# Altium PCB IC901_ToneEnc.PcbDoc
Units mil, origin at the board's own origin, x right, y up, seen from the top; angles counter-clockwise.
Board outline 1200 x 900 mil, 2 copper layers (Top Layer, Bottom Layer), stack 30.2 mil thick; 35 components, 32 nets, 99 pads, 51 vias.
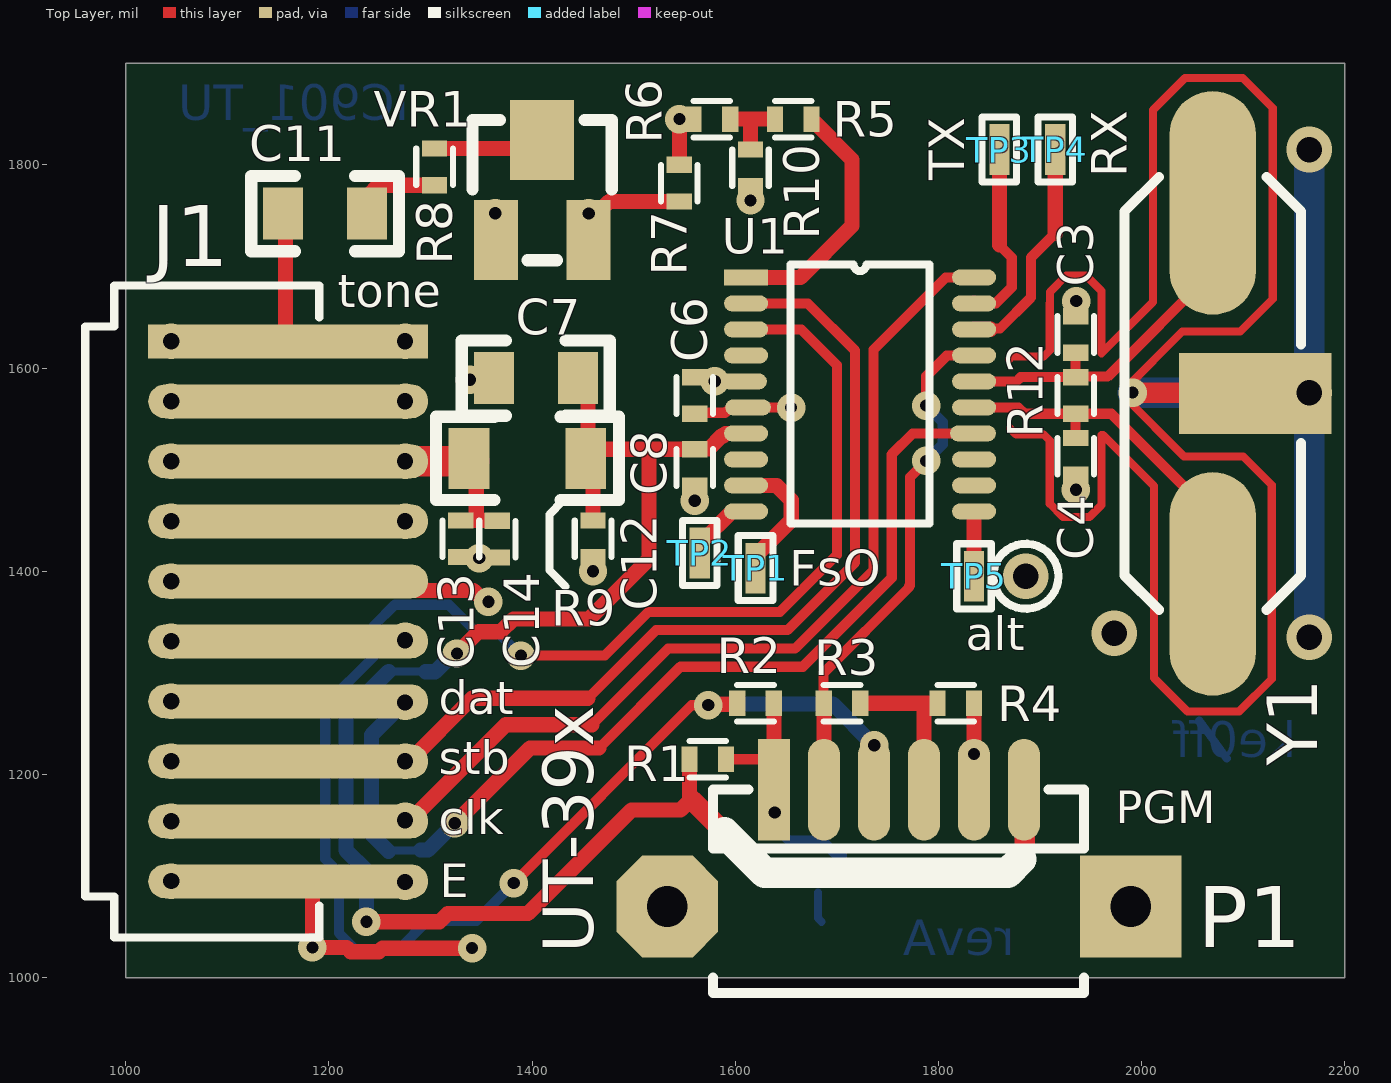
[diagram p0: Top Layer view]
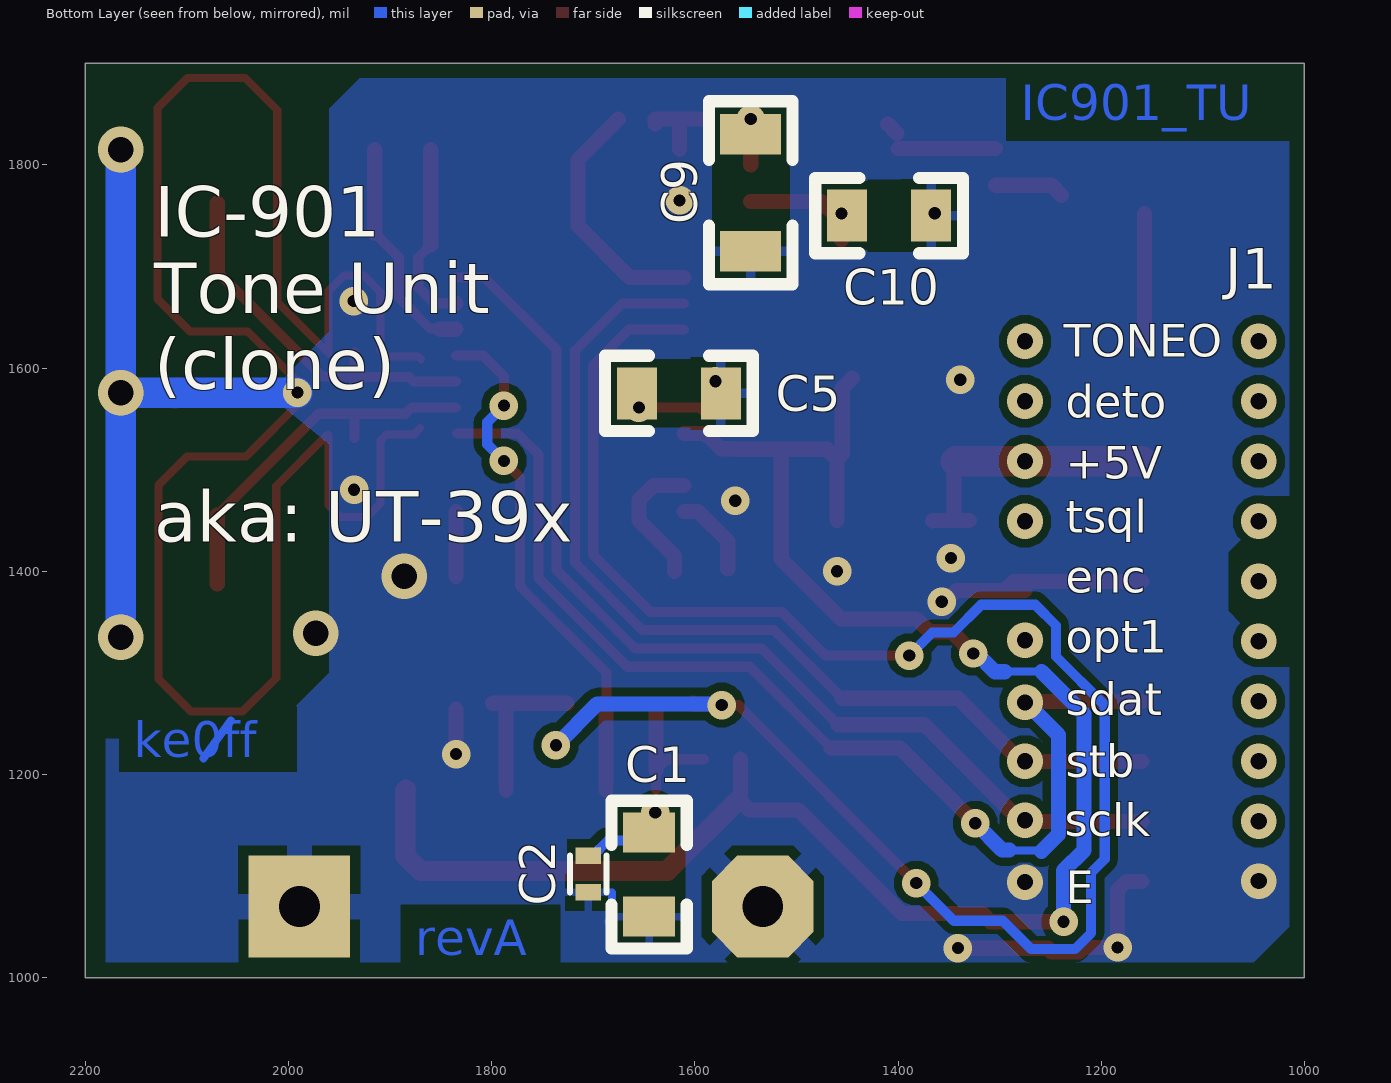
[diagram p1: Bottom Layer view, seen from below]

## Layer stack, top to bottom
Top Solder: solder mask 0.4, Solder Resist, Dk 3.5
Top Layer: signal copper 1.4
Dielectric 1: dielectric 27.4, FR-4, Dk 4.8
Bottom Layer: signal copper 1.4
Bottom Solder: solder mask 0.4, Solder Resist, Dk 3.5

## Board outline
1000,1000 1000,1900 2200,1900 2200,1000

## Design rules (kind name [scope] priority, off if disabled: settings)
Clearance [All] p1: gap=8 ignorepadtopadclearanceinfootprint=FALSE
HoleSize [All] p1: absolutevalues=TRUE maxlimit=275 minlimit=12 maxpercent=80.000 minpercent=20.000
MinimumSolderMaskSliver [All] p1: minsoldermaskwidth=1
NetAntennae [All] p1: netantennaetolerance=400
PolygonConnect PolygonConnect_2 [IsVia] p1: connectstyle=Direct reliefconductorwidth=10 reliefentries=4 polygonreliefangle="90 Angle" airgapwidth=10
PolygonConnect [IsPad] p2: connectstyle=Relief reliefconductorwidth=20 reliefentries=4 polygonreliefangle="45 Angle" airgapwidth=10
PolygonConnect PolygonConnect_1 [All] p3: connectstyle=Relief reliefconductorwidth=10 reliefentries=4 polygonreliefangle="90 Angle" airgapwidth=10
RoomDefinition IC901_ToneEnc [InComponentClass('IC901_ToneEnc')] p1: confinementstyle=ConfineOut formatcopy=TRUE lockcomponents=FALSE outline 0,0 445,0 445,200 0,200
RoutingVias [All] p1: holewidth=12 width=25 viastyle="Through Hole" minholewidth=12 minwidth=24 maxholewidth=100 maxwidth=150
SilkToSilkClearance [All] p1: silktosilkclearance=0
SilkToSolderMaskClearance [IsPad] p1: minsilkscreentomaskgap=0 clearancetoexposedcopper=TRUE
SolderMaskExpansion [All] p1: expansion=4 istentingtop=FALSE
Width [All] p1: maxlimit=100 minlimit=8 preferedwidth=10 minimp=50.000000 maximp=50.000000 favimp=50.000000
25 further rules are at their usual default settings.

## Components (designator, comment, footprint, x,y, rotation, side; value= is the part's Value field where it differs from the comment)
C1 "1.0uF" 0805 1645,1142.68 r270 bottom
C2 "0.1uF" 0402 1705,1120 r270 bottom
C3 "22pF" 0402 1935,1615 r90 top
C4 "22pF" 0402 1935,1531 r270 top
C5 "4.7uF" 0805 1657,1575 r180 bottom
C6 "0.1uF" 0402 1560,1555 r90 top
C7 "4.7uF" 0805 1445,1590 r180 top
C8 "0.1uF" 0402 1560,1520 r270 top
C9 "0.047uF" 1206 1545,1830 r270 bottom
C10 "4700pF" 0805 1450,1750 r180 bottom
C11 "1.0uF" 0805 1237.68,1752 r180 top
C12 "0.1uF" 0402 1460,1450 r270 top
C13 "0.1uF" 0402 1330,1450 r270 top
C14 "1000pF" 0402 1365.88,1449.61 r270 top
J1 "TONE" MOLEX_1.5MM_SMD_10POS 1160,1094.72 r0 top
P1 "PGM" CON_1.25MM_6P 1638.15,1185 r0 top
R1 "1.00K" 0402 1591,1215 r180 top
R2 "1.00K" 0402 1602,1270 r0 top
R3 "1.00K" 0402 1687,1270 r0 top
R4 "100K" 0402 1835,1270 r180 top
R5 "499" 0402 1639,1845 r0 top
R6 "909" 0402 1559,1845 r0 top
R7 "13.7K" 0402 1545,1764 r90 top
R8 "47K" 0402 1304,1780 r90 top
R9 "10" 1206 1338,1511 r0 top
R10 "330" 0402 1615,1815 r270 top
R12 "10.0M" 0402 1935,1591 r270 top
TP1 "FsO" TP-SMD-20x50-SQ 1620,1403 r180 top
TP2 "SPr15" TP-SMD-20x50-SQ 1565,1418 r180 top
TP3 "TX" TP-SMD-20x50-SQ 1860,1815 r180 top
TP4 "RX" TP-SMD-20x50-SQ 1915,1815 r180 top
TP5 "SPr14" TP-SMD-20x50-SQ 1835,1395 r180 top
U1 "C8051F530" TSSOP-20 1610.59,1689.13 r0 top
VR1 "47K" POT_3313 1364.5,1726 r180 top
Y1 "3.5795M" XTAL_AT49_SMD 2070,1575 r90 top

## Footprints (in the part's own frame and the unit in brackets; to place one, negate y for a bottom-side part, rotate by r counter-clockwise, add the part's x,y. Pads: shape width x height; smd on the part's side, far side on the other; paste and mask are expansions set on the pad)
0402 [mil]
  rect 16x25 smd mask+2: 1(0,0) 2(36,0)
  silkscreen extent 0,-18 36,18, body extent -2,-10 38,10, height 10
0805 [mm]
  rect 1x1.3 smd: 1(0,0) 2(2.1,0)
  silkscreen extent -0.8,-0.94 2.9,0.94, body extent -0.03,-0.64 2.13,0.63, height 0.51
1206 [mil]
  rect 40x60 smd: 1(0,0) 2(115,0)
  silkscreen extent -33,-41 148,41, body extent -3,-30 117,30, height 30
CON_1.25MM_6P [mm]
  rect 0.8x2.54 smd: 1(0,0)
  oval 0.8x2.54 smd: 2(1.25,0) 3(2.5,0) 4(3.75,0) 5(5,0) 6(6.25,0)
  oct 2.54x2.54 hole 1.016: 7(-2.667,-2.921)
  rect 2.54x2.54 hole 1.016: 8(8.915,-2.921)
  silkscreen extent -1.52,-5.08 7.75,0, body extent -2.96,-4.41 9.19,0.49, height 4.79
MOLEX_1.5MM_SMD_10POS [mm]
  rect 7x0.85 smd mask-10: 1(0,13.5)
  oval 7x0.85 smd mask-10: 2(0,12) 3(0,10.5) 4(0,9) 5(0,7.5) 6(0,6) 7(0,4.5) 8(0,3) 9(0,1.5) 10(0,0)
  silkscreen extent -5.07,-1.4 0.77,14.9, body extent -5.02,-1.4 2.73,14.9, height 4.52
POT_3313 [mil]
  rect 43x78.74 smd: 1(0,0) 3(-91,0)
  rect 63x78.74 smd: 2(-45.5,-98.27)
  silkscreen extent -114,-118 23,20, body extent -108,-118 22,20, height 87
TP-SMD-20x50-SQ [mil]
  rect 20x50 smd mask+2: 1(0,0)
  silkscreen extent -17,-32 17,32
TSSOP-20 [mm]
  rect 1.1x0.4 smd mask+0.051: 1(0,0)
  oval 1.1x0.4 smd mask+0.051: 2(0,-0.65) 3(0,-1.3) 4(0,-1.95) 7(0,-3.9) 8(0,-4.55) 9(0,-5.2) 10(0,-5.85) 11(5.7,-5.85) 12(5.7,-5.2) 13(5.7,-4.55) 15(5.7,-3.25) 16(5.7,-2.6) 17(5.7,-1.95) 18(5.7,-1.3) 19(5.7,-0.65) 20(5.7,0)
  oval 1.143x0.4 smd mask+0.051: 5(-0.051,-2.6) 6(0.051,-3.25) 14(5.675,-3.9)
  silkscreen extent 1.11,-6.15 4.59,0.32, body extent -0.35,-6.1 6.05,0.27, height 1.2
XTAL_AT49_SMD [mil]
  oval 220x85 smd mask+2: 1(-187.5,0) 2(187.5,0)
  rect 80x150 smd mask+2: 3(0,-42)
  silkscreen extent -213,-87 213,87, body extent -276,-87 276,87, height 134

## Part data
C1 C11: library part "CAP 0805", "CAP, CER, 0805, 1.0uF, 25V", MFR=Samsung, MPN=CL21B105KBFNNNF, Voltage=25V
C2 C6 C8 C12 C13: library part "CAP CER", "CAP, CER, 0402, 0.1uF, 50V", MFR=AVX, MPN=04025C104KAT2A
C3 C4: library part "CAP 0805", "CAP, MLCC, NPO, 1%, 0402, 50V, 22pF", MFR=Murata, MPN=GCM1555C1H220FA16D, Voltage=50
C5 C7: library part "CAP 0805", "CAP, CER, 0805, 4.7uF, 10V", MFR=TDK, MPN=C2012X7R1A475K125AC, Voltage=10V
C9: library part "CAP 0805", "CAP, CER, NPO, 0805, 50V, 47nF", MFR=Yageo, MPN=CC1206JKNPO9BN473, Voltage=50V
C10: library part "CAP 0805", "CAP, CER, 0805, NPO, 50V, 4700pF", MFR=Walsin, MPN=0805N472J500CT, Voltage=50V
C14: library part "CAP CER", "CAP, CER, 0402, 50V, 1000pF", MFR=Yageo, MPN=CC0402JRNPO9BN102
J1: library part CON10, "CON, 10POS, 1.5mm, RTANG, SMT", MFR=Molex, MPN=87438-1043
P1: library part HEADER-6-PIN-RT-ANG, "CON, 6POS, 1.25MM, SMD", MFR=Molex, MPN=53398-0671
R1 R2 R3: library part R0805, "RES, CHP, 0402, 1%, 1K", MFR=Yageo, MPN=RC0402FR-071KL
R4: library part R0805, "RES, CHP, 0402, 1%, 100K", MFR=Yageo, MPN=RC0402FR-07100KL
R5: library part R0805, "RES, CHP, 0402, 1%, 499", MFR=Yageo, MPN=RC0402FR-07499RL
R6: library part R0805, "RES, CHP, 0402, 1%, 909", MFR=Yageo, MPN=RC0402FR-07909RL
R7: library part R0805, "RES, CHP, 0402, 1%, 13.7K", MFR=Yageo, MPN=RC0402FR-0713K7L
R8: library part R0805, "RES, CHP, 0402, 1%, 47K", MFR=Yageo, MPN=RC0402FR-0747KL
R9: library part R0805, "RES, CHP, 0402, 1%, 10.0", MFR=Yageo, MPN=RC1206FR-7W10RL
R10: library part R0805, "RES, CHP, 0402, 1%, 330", MFR=Yageo, MPN=RC0402FR-07330RL
R12: library part R0805, "RES, CHP, 0402, 1%, 10.0M", MPN=RC0402FR-0710ML
TP1 TP2 TP3 TP4 TP5: library part TP
U1: library part C8051F531, "IC, MCU, 8051, F531", MFR=SiLabs, MPN=C8051F531-C-IT
VR1: library part "RESISTOR VAR", MFR=Bourns, MPN=3313X-1-503E
Y1: library part CRYSTAL-2PIN, "CRYSTAL 2 PIN", MFR=Abracon, MPN=ABLSG-3.579545MHZ-D2Y-T

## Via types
v1: diameter 28, hole 12, Top Layer to Bottom Layer, tented both sides, 27 vias
v2: diameter 35, hole 16, Top Layer to Bottom Layer, 19 vias
v3: diameter 45, hole 25, Top Layer to Bottom Layer, 5 vias

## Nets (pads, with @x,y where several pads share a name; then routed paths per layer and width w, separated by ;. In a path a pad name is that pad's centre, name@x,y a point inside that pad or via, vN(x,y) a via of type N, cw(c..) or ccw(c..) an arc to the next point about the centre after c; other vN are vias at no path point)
+5V_IN: C13.1 C14.1 J1.3 R9.1 | length 283.2
  Top Layer w15: C13.1 1330.2,1449.8 1347.94,1449.8 ; R9.1@1336.11,1509.11 R9.1 ; R9.1@1345,1510 1345,1452.74 1347.94,1449.8 ; C14.1 1365.68,1449.8 1347.94,1449.8
  Top Layer w30: J1.3 v2(1275,1508.11) R9.1@1343.11,1508.11
  other v2: 1045,1508.11
/RESET: C1.1 C2.1 P1.1 R1.1 R2.2 | length 199.3
  Top Layer w10: R1.1 1627.4,1215 1638.15,1204.25 P1.1
  Top Layer w15: P1.1@1638.15,1204.25 R2.2@1638.15,1263.35
  Bottom Layer w10: C1.1 1652.68,1135 1685.5,1135 1700.5,1120 C2.1
  other v1: 1638.92,1162.44
/RST_C2K: P1.3 R2.1 U1.3 | length 1812.7
  Top Layer w10: v1(1382,1093) 1557,1268 v1@1563.4,1268 ; v1(1389,1317) 1471.54,1317 1514.54,1360 1644,1360 1700,1416 1700,1603 1665.05,1637.95 U1.3
  Top Layer w15: v1(1573.44,1268.28) 1574.31,1269.14 1601.5,1269.14 1602,1269.64 R2.1
  Bottom Layer w10: v1(1382,1093) 1345,1056 1296.97,1056 1268.97,1028 1225.82,1028 1210,1043.82 1210,1103.27 1196.5,1116.77 1196.5,1268.05 1244.5,1316.05 1244.5,1346.5 1265,1367 1318,1367 1345.31,1339.69 1366.31,1339.69 v1(1389,1317)
  Bottom Layer w15: v1@1574.44,1269.27 1696.07,1269.27 v1(1736.73,1228.61)
DETO: J1.2
  other v2: 1045,1567.17 1275,1567.17
fsamp_out: TP1.1 U1.9 | length 134.9
  Top Layer w15: U1.9 1610.73,1484.27 1640.73,1484.27 1655,1470 1655,1450 1620,1415 TP1.1@1620,1400
GND: C1.2 C2.2 C3.2 C4.2 C5.2 C6.2 C7.2 C8.2 C9.2 C10.2 C12.2 C13.2 C14.2 J1.5 J1.10 P1.5 P1.7 P1.8 R4.1 R10.2 U1.5 VR1.1 Y1.3 | length 3342.3
  Top Layer w8: 1869.65,1608.64 1872.51,1611.5 1903.64,1611.5 1909.5,1617.36 1909.5,1649.75 1909.5,1663.77 1909.65,1663.92 1909.65,1674.91 1925.77,1691.03 1945.11,1691.03 1960.5,1675.63 1960.5,1638.38 1960.5,1614.5 2011,1664.99 2011,1854 2042.5,1885.5 2099.5,1885.5 2129,1856 2129,1668 2097,1636 2039.99,1636 v1@1983.51,1579.52 ; 1870.33,1540.68 1876.51,1534.5 1903.64,1534.5 1909.5,1528.64 1909.5,1466.46 1922.73,1453.23 1948.7,1453.23 1960.5,1465.03 1960.5,1534 ; 1962.01,1534 2012,1484.01 2012,1295 2045,1262 2096,1262 2128,1294 2128,1485 2100,1513 2041.75,1513 v1@1983.51,1571.23
  Top Layer w10: v1@1935,1661 C3.2@1938,1658 ; v1@1983.51,1571.23 v1@1983.51,1579.52
  Top Layer w15: J1.10 1175.35,1094.72 1183.88,1086.19 v1(1183.88,1029.63) 1217.39,1029.63 1221.53,1025.5 1249.22,1025.5 1252.72,1029 v1(1341,1029) ; J1.5 1286.06,1390 J1.5@1295.06,1381 ; J1.5@1275.06,1381 1342.48,1381 1353.48,1370 v1(1357,1370) ; v1(1835,1220) R4.1@1835,1264.5
  Top Layer w20: v1(1991.1,1575.76) Y1.3@2108.24,1575.76
  Top Layer w30: Y1.3@2108.24,1575.76 Y1.3
  Bottom Layer w8: 1681.42,1083.93 1681.42,1058.58 1685,1055
  Bottom Layer w30: v1(1991.1,1575.76) v3(2165,1575.76) ; v3(2165,1335) v3(2165,1575.76) ; v3(2165,1815) v3(2165,1575.76)
  other v1: 1460,1400 1347.95,1412.96 1560.19,1469.27 1935.34,1480.13 1579.75,1586.88 1338.81,1588.4 1935.6,1665.85 1363.81,1752.38 1615,1765
  other v2: 1275,1094 1045,1095 1045,1390
  other v3: 1973,1339 1886,1395
M5V: C7.1 C8.1 C12.1 P1.6 R1.2 R9.2 U1.7 | length 1829.5
  Top Layer w15: v1(1237,1055) 1309,1055 1317,1063 1396,1063 1498,1165 1546.21,1165 1555,1173.79 1555,1176.95 ; v1(1326,1319) 1347.5,1340.5 1369.22,1340.5 1381.72,1353 1456,1353 1515,1412 1515,1520 ; C7.1 1455,1580 1455,1515 R9.2@1460,1510 ; C12.1 R9.2@1460,1510 ; R1.2 1555,1176.95 ; 1557.5,1174.45 1555,1176.95 ; U1.7 1610.45,1535.45 1590.45,1535.45 1588.37,1533.37 1587.13,1533.37 1574.26,1520.5 1560.5,1520.5 C8.1 1515,1520 ; R9.2@1460,1510 1470,1520 1515,1520
  Top Layer w20: 1557.5,1174.45 1626.95,1105 1870,1105 1885,1120 1885,1184.21 P1.6
  Bottom Layer w8: 1258.86,1301.42 1294.58,1301.42 1295,1301
  Bottom Layer w15: v1(1237,1055) 1237,1105.26 1217,1125.26 1217,1259.56 1258.86,1301.42 ; 1295,1301 1304.48,1301 1322.48,1319 v1(1326,1319)
NetC3_1: C3.1 R12.1 U1.16 Y1.2 | length 371.3
  Top Layer w10: U1.16 1876.77,1586.77 1881,1591 R12.1 C3.1 ; R12.1@1935.5,1591.5 1966.5,1591.5 Y1.2@2070,1695
  Top Layer w15: R12.1 R12.1@1935.5,1591.5 ; Y1.2@2070,1695 Y1.2
NetC4_1: C4.1 R12.2 U1.15 Y1.1 | length 370.5
  Top Layer w10: U1.15 1878.82,1561.18 1885,1555 R12.2 ; C4.1 R12.2 ; Y1.1@2070,1455 1970,1555 R12.2
  Top Layer w15: Y1.1 Y1.1@2070,1455
NetC5_1: C5.1 C6.1 U1.6 | length 95.6
  Top Layer w10: C6.1 1560.95,1555.95 1590.02,1555.95 1595.26,1561.18 U1.6@1610.59,1561.18 ; U1.6 1612.68,1561.09 1654.91,1561.09 v1(1655,1561)
NetC9_1: C9.1 R6.1 R7.2 | length 45
  Top Layer w15: R7.2 v1(1545,1845)
NetC10_1: C10.1 R7.1 VR1.3 | length 125.4
  Top Layer w15: VR1.3 VR1.3@1455.5,1742.5 ; v1(1455.71,1752.14) 1455.5,1751.93 VR1.3@1455.5,1742.5 ; R7.1 1475.63,1764 1460.21,1748.59 1460.21,1747.21 VR1.3@1455.5,1742.5
NetC11_1: C11.1 R8.1 | length 69.1
  Top Layer w15: C11.1@1239,1770 1249,1780 R8.1
NetR5_1: R5.1 R6.2 R10.1 | length 75
  Top Layer w15: R6.2 R5.1 R5.1@1639,1840.5 ; R10.1 1615,1841.5
NetR8_2: R8.2 VR1.2 | length 108.7
  Top Layer w15: R8.2 VR1.2@1400,1816 ; VR1.2@1401,1831 VR1.2@1410,1840
OPT1: J1.6
  other v2: 1045,1330.94 1275,1331.94
P0.6_C2D: P1.2 R3.1 U1.17 | length 514.9
  Top Layer w10: R3.1@1690,1273 R3.1 1687,1300 1771,1384 1771,1385.18 1772,1386.18 1772,1492.62 v1(1787.94,1508.56) ; v1(1787.94,1563) 1787.94,1591.94 1808.18,1612.18 1834.82,1612.18 U1.17
  Top Layer w15: P1.2 R3.1@1687.36,1262.86
  Bottom Layer w10: v1(1787.94,1508.56) 1804.3,1524.92 1804.3,1546.65 v1(1787.94,1563)
PWMDAC: R5.2 U1.1 | length 247
  Top Layer w15: U1.1 1664.13,1689.13 1715,1740 1715,1805 R5.2
SCLK: J1.9 U1.20 | length 1023.8
  Top Layer w10: 1459,1249 1534,1324 1658.91,1324 1736,1401.09 1736,1618 1807.13,1689.13 U1.20
  Top Layer w15: J1.9 1278.99,1153.78 1374.21,1249 1459,1249
  other v2: 1045,1153.78 1275,1154.78
SDAT: J1.7 U1.14 | length 1099.8
  Top Layer w10: 1466,1226 1546,1306 1666.37,1306 1754,1393.63 1754,1515 1774.59,1535.59 U1.14
  Top Layer w15: J1.7 J1.7@1275,1271.89 ; v1(1324,1152) 1398,1226 1466,1226
  Bottom Layer w8: 1258.72,1124.39 1262.39,1124.39 1263.28,1125.28 1287.22,1125.28 1287.42,1125.48 1290.19,1125.48
  Bottom Layer w15: 1258.72,1124.39 1242,1141.11 1242,1238.89 v2@1275,1271.89 ; 1290.19,1125.48 1297.48,1125.48 v1(1324,1152)
  other v2: 1275,1270.89 1045,1271.89
SPARE_04: TP3.1 U1.19 | length 184.3
  Top Layer w10: U1.19@1835.14,1663.69 1856.39,1663.69 1872.15,1679.45 1872.15,1708.85 1860,1721
  Top Layer w15: U1.19 U1.19@1835.14,1663.69 ; 1860,1721 TP3.1
SPARE_05: TP4.1 U1.18 | length 225.1
  Top Layer w10: U1.18@1851.31,1638.1 1851.31,1638.93 1860.62,1638.93 1891,1669.31 1891,1708.57 1915,1732.57
  Top Layer w15: U1.18 1835.14,1638.1 U1.18@1851.31,1638.1 ; 1915,1732.57 TP4.1
SPARE_06: P1.4 R3.2 R4.2 | length 158
  Top Layer w15: R3.2@1726,1270 1785.79,1270 ; P1.4 1785.79,1270 ; R4.2 1785.79,1270
SPARE_12: U1.13
SPARE_13: U1.12
SPARE_14: TP5.1 U1.11 | length 63.8
  Top Layer w15: TP5.1 U1.11
SPARE_15: TP2.1 U1.10 | length 82.2
  Top Layer w15: TP2.1@1567.5,1402.5 1567.5,1429.51 1596.81,1458.82 U1.10
SPARE_17: U1.8
STB: J1.8 U1.2 | length 980.3
  Top Layer w10: 1455,1275 1522,1342 1651.46,1342 1718,1408.54 1718,1617 1671.46,1663.54 U1.2
  Top Layer w15: J1.8 J1.8@1281.06,1212.83 ; v2(1275,1212.83) 1278.92,1212.83 1341.08,1275 1455,1275
  other v2: 1045,1212.83
TONE_OUT: C11.2 J1.1 | length 126.9
  Top Layer w15: C11.2@1157.32,1752 1157.32,1628.9 J1.1
  other v2: 1045,1626.22 1275,1626.22
TSQL: J1.4
  other v2: 1045,1449.06 1275,1449.06
VREF: U1.4
copper on no net: | length 45.8
  Bottom Layer w8: 2056.72,1252.83 2083.72,1215.83

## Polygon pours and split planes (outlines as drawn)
GND on Bottom Layer "NONET_L-01_P-001" (solid, remove dead copper, pour order 0): 1050,1015 2180,1015 2180,1235 2025,1235 1960,1300 1960,1525 2010.11,1565.62 2009.89,1584.33 1959.56,1636.23 1960,1855 1930,1885 1050,1885 1015,1850 1015,1474.39 1045,1474.39 1045,1448.77 1075,1418.77 1075,1360.94 1045,1330.94 1045,1305.26 1015,1305.26 1015,1050 1045,1020

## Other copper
Bottom Layer:
  pour cut-out: 1674.96,1088.28 1725.5,1088.28 1725.5,1115 1675.02,1115
  pour cut-out: 1609.41,1125 1676.75,1125 1676.75,1075.54 1609.41,1075.54
  pour cut-out: 1590,1541.41 1640,1541.41 1640,1608.51 1590,1608.51
  pour cut-out: 1506.78,1735 1506.78,1810 1583.02,1810 1583.02,1735
  pour cut-out: 1384.96,1785.54 1429.96,1785.54 1429.96,1714.55 1384.96,1714.55
  text "IC901_TU" at 1279,1843.83 h35
  text "ke0ff" at 2152,1217 h35
  text "revA" at 1875,1022 h35

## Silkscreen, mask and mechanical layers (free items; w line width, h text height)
Top Overlay:
  circle w8: c1886,1395 r32
  lines w8: 1433,1385 1417,1401 1417,1456 1430,1469 1435,1469
  lines w30: 1589,1143 1629,1103 1866,1103 ; 1868,1103 1881.5,1116.5
  text "tone" at 1209,1660 h33
  text "alt" at 1827,1322 h33
  text "dat" at 1308,1259.06 h33
  text "stb" at 1308,1200 h33
  text "clk" at 1308,1140.94 h33
  text "E" at 1309,1079 h33
  text "UT-39x" at 1460,1024 h50 r90
Bottom Overlay:
  text "J1" at 1078,1678 h40
  text "TONEO" at 1237,1611 h32
  text "deto" at 1235,1551 h32
  text "+5V" at 1235,1491 h32
  text "tsql" at 1235,1437.65 h32
  text "IC-901 / Tone Unit / (clone) /  / aka: UT-39x" at 2132,1429 h50
  text "enc" at 1235,1379 h32
  text "opt1" at 1235,1319.83 h32
  text "sdat" at 1235,1258 h32
  text "stb" at 1235,1197 h32
  text "sclk" at 1236,1139 h32
  text "E" at 1235,1073.22 h32
Board Outline:
  the board outline again, w1
Drill Drawing:
  drawing of 371 lines, arcs and shapes, not listed
  text "Symbol" at 672.47,5812.8 h50.79
  text "Count" at 1038.77,5812.8 h50.79
  text "Hole Size" at 1425.52,5812.8 h50.79
  text "Plated" at 2207.19,5812.8 h50.79
  text "Hole Type" at 2573.49,5812.8 h50.79
  text "Drill Layer Pair" at 3100.59,5812.8 h50.79
  text "Via/Pad" at 4164.36,5812.8 h50.79
  text "Pad Shape" at 4589.9,5812.8 h50.79
  text "Template" at 5125.46,5812.8 h50.79
  text "Description" at 5653.25,5812.8 h50.79
  text "Hole Tolerance (+)" at 6264.98,5812.8 h50.79
  text "Hole Tolerance (-)" at 7215.22,5812.8 h50.79
  text "2" at 1038.77,5706.98 h42.33
  text "40.00mil (1.016mm)" at 1425.52,5706.98 h42.33
  text "PTH" at 2207.19,5706.98 h42.33
  text "Round" at 2573.49,5706.98 h42.33
  text "Top Layer - Bottom Layer" at 3100.59,5706.98 h42.33
  text "Pad" at 4164.36,5706.98 h42.33
  text "(Mixed)" at 4589.9,5706.98 h42.33
  text "(Mixed)" at 5125.46,5706.98 h42.33
  text "5" at 1038.77,5601.16 h42.33
  text "25.00mil (0.635mm)" at 1425.52,5601.16 h42.33
  text "PTH" at 2207.19,5601.16 h42.33
  text "Round" at 2573.49,5601.16 h42.33
  text "Top Layer - Bottom Layer" at 3100.59,5601.16 h42.33
  text "Via" at 4164.36,5601.16 h42.33
  text "Rounded" at 4589.9,5601.16 h42.33
  text "v114h64m124" at 5125.46,5601.16 h42.33
  text "19" at 1038.77,5495.34 h42.33
  text "16.00mil (0.406mm)" at 1425.52,5495.34 h42.33
  text "PTH" at 2207.19,5495.34 h42.33
  text "Round" at 2573.49,5495.34 h42.33
  text "Top Layer - Bottom Layer" at 3100.59,5495.34 h42.33
  text "Via" at 4164.36,5495.34 h42.33
  text "Rounded" at 4589.9,5495.34 h42.33
  text "v89h41m99" at 5125.46,5495.34 h42.33
  text "27" at 1038.77,5389.52 h42.33
  text "12.00mil (0.305mm)" at 1425.52,5389.52 h42.33
  text "PTH" at 2207.19,5389.52 h42.33
  text "Round" at 2573.49,5389.52 h42.33
  text "Top Layer - Bottom Layer" at 3100.59,5389.52 h42.33
  text "Via" at 4164.36,5389.52 h42.33
  text "Rounded" at 4589.9,5389.52 h42.33
  text "v71h30m0mx0" at 5125.46,5389.52 h42.33
  text "53 Total" at 1038.77,5283.7 h42.33
  text "Layer" at 651.18,5166.19 h34.11
  text "Name" at 892.83,5166.19 h34.11
  text "Material" at 1429.99,5166.19 h34.11
  text "Thickness" at 1927.36,5166.19 h34.11
  text "Constant" at 2305.4,5166.19 h34.11
  text "Board Layer Stack" at 2637.98,5166.19 h34.11
  text "Top Overlay" at 892.83,5097.98 h34.11
  text "Top Solder" at 892.83,5029.76 h34.11
  text "Solder Resist" at 1429.99,5029.76 h34.11
  text "0.40mil" at 1927.36,5029.76 h34.11
  text "3.5" at 2305.4,5029.76 h34.11
  text "1" at 651.18,4961.55 h34.11
  text "Top Layer" at 892.83,4961.55 h34.11
  text "1.40mil" at 1927.36,4961.55 h34.11
  text "Dielectric 1" at 892.83,4893.33 h34.11
  text "FR-4" at 1429.99,4893.33 h34.11
  text "27.40mil" at 1927.36,4893.33 h34.11
  text "4.8" at 2305.4,4893.33 h34.11
  text "2" at 651.18,4825.12 h34.11
  text "Bottom Layer" at 892.83,4825.12 h34.11
  text "1.40mil" at 1927.36,4825.12 h34.11
  text "Bottom Solder" at 892.83,4756.9 h34.11
  text "Solder Resist" at 1429.99,4756.9 h34.11
  text "0.40mil" at 1927.36,4756.9 h34.11
  text "3.5" at 2305.4,4756.9 h34.11
  text "Bottom Overlay" at 892.83,4688.68 h34.11
  text "Total board thickness:" at 651.18,4620.47 h34.11
  text "31.00mil" at 1927.36,4620.47 h34.11
  text "IC-901 Tone Unit (RevA) CONTACT INFO:" at 3606,4229.33 h100
  text "Joe Haas" at 3606,3996 h100
  text "joeh@rollanet.org" at 3606,3796 h100
  text "4301 Yellowstone Dr." at 3606,3596 h100
  text "Taylor, TX 76574" at 3606,3396 h100
  text "+1 512-577-5575" at 3606,3196 h100
  text "IC901_TU, RevA PCB FAB Notes:" at 3541,2854.33 h58.33
  text "ALL DIMENSIONS IN MILS UNLESS NOTED." at 3541,2746 h58.33
  text "MTL: FR-4, 0.031 (0,8mm) THK +/- 5%" at 3541,2654.33 h58.33
  text "BOARD EDGE DIMENSION TOLERANCE: +/- 10%" at 3541,2551 h58.33
  text "NUMBER OF COPPER LAYERS: 2, WT: 1 OZ" at 3541,2451 h58.33
  text "FINISH: LEADED HASL (LEAD-FREE OR ENIG MAY BE SUBSTITUTED)" at 3541,2351 h58.33
  text "SOLDERMASK: SMOBC, TWO SIDES, GREEN" at 3541,2251 h58.33
  text "SILKSCREEN: 2-SIDE, WHITE" at 3541,2151 h58.33
  text "(30,48mm)" at 1374,2073.99 h60
  text "HOLE SIZES ARE FINISHED DIMENSION" at 3541,2051 h58.33
  text "BOARD OUTLINE IS 1mil TRACE ON ALL PLOT LAYERS.  REMOVE FOR FAB" at 3541,1952 h58.33
  text "GERBER LAYER MAP:" at 3541,1596 h58.33
  text "IC901_TU.GTO" at 5241,1515.44 h58.33
  text "TOP SILK: . . . . . . . . . . . . . . . . . . ." at 3541,1496 h58.33
  text "IC901_TU.GTS" at 5241,1415.02 h58.33
  text "TOP SOLDERMASK: . . . . . . . . . . . . . ." at 3541,1395.58 h58.33
  text "IC901_TU.GTL" at 5241,1314.61 h58.33
  text "TOP COPPER: . . . . . . . . . . . . . . . . ." at 3541,1295.17 h58.33
  text "IC901_TU.GBL" at 5241,1214.19 h58.33
  text "(22,86mm)" at 2780.01,1201 h60 r90
  text "BOTTOM COPPER: . . . . . . . . . . . . . ." at 3541,1194.75 h58.33
  text "IC901_TU.GBS" at 5241,1113.77 h58.33
  text "BOTTOM SOLDERMASK: . . . . . . . . . . ." at 3541,1094.33 h58.33
  text "IC901_TU.GBO" at 5241,1013.35 h58.33
  text "BOTTOM SILK: . . . . . . . . . . . . . . . . ." at 3541,993.91 h58.33
  text "IC901_TU.TXT" at 5241,912.94 h58.33
  text "DRILL FILE: . . . . . . . . . . . . . . . . . . ." at 3541,893.5 h58.33
  text "IC901_TU.DRR  (HOLE TOLERANCE +0/-0.003)" at 5241,800.44 h58.33
  text "DRILL TOOL FILE: . . . . . . . . . . . . . . ." at 3541,793.08 h58.33
  text "IC901_TU.GD1  (THIS DWG)" at 5241,695.44 h58.33
  text "DRILL/FAB DRAWING: . . . . . . . . . . . . ." at 3541,684.33 h58.33
  text "PLACE PCB FAB DATE/MFR CODE ON BACK-SIDE SILKSCREEN" at 3541,396 h58.33

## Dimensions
1000,1900 to 2200,1900 on Drill Drawing
2200,1000 to 2200,1900 on Drill Drawing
